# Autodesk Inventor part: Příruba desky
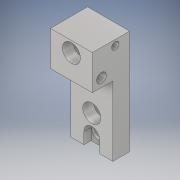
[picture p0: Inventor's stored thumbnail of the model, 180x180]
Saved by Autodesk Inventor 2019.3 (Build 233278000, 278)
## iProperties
Created: 2019-01
Part Number: Příruba desky
Material: Hliník 6061-AHC
Document SubType Name: Modeling
Designer: B-hon
Density: 2.7 g/cm^3
Appearance: Hliník – tmavý
Author: B-hon
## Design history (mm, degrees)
sketch "Náčrt1"
  geometry: L1 (-32.5, 40)-(32.5, 40); L2 (32.5, 40)-(32.5, -40); L3 (32.5, -40)-(-32.5, -40); L4 (-32.5, -40)-(-32.5, 40); L5 (-32.5, 40)-(32.5, -40); L6 (32.5, 40)-(-32.5, -40); 1 further point
  constraints: 12 end point, 2 midpoint, 2 parallel, 1 horizontal, 1 perpendicular
  dimensions: "d0" = 65 distance of L2.end L3.end; "d1" = 80 distance of L1.end L2.end
extrude "Vysunutí1" new body sketch "Náčrt1" distance "d2" = 26; taper "d3" = 0 deg
sketch "Náčrt2"
  geometry: L1 (-44.381, 28)-(47.748, 28); L2 (47.748, 28)-(47.748, 22); L3 (47.748, 22)-(-44.381, 22); L4 (-44.381, 22)-(-44.381, 28); L5 (-44.381, 28)-(47.748, 22); L6 (47.748, 28)-(-44.381, 22); L7 (-32.5, -40)-(32.5, -40) reference; L8 (-38.512, 18)-(43.239, 18); L9 (43.239, 18)-(43.239, -45.522); L10 (43.239, -45.522)-(-38.512, -45.522); L11 (-38.512, -45.522)-(-38.512, 18); L12 (-32.5, 40)-(-32.5, -40) reference; 2 further points
  constraints: 20 end point, 4 parallel, 2 horizontal, 2 midpoint, 2 perpendicular
  dimensions: "d4" = 6 distance of L1.end L2.end; "d5" = 65 distance from line of L7 point (1.683, 25); "d6" = 7 distance from line of L8 point (1.683, 25)
extrude "Vysunutí2" cut sketch "Náčrt2" distance "d10" = 14; taper "d11" = 0 deg
sketch "Náčrt3"
  geometry: L1 (-39.607, 44.84)-(-17.5, 44.84); L2 (-17.5, 44.84)-(-17.5, 11.926); L3 (-17.5, 11.926)-(-39.607, 11.926); L4 (-39.607, 11.926)-(-39.607, 44.84); L5 (17.5, 44.045)-(36.686, 44.045); L6 (36.686, 44.045)-(36.686, 9.931); L7 (36.686, 9.931)-(17.5, 9.931); L8 (17.5, 9.931)-(17.5, 44.045); L9 (-32.5, 40)-(-32.5, 18) reference; 1 further point
  constraints: 16 end point, 4 parallel, 2 horizontal, 2 perpendicular
  dimensions: "d12" = 35 distance between parallel lines of L8 L2; "d13" = 15 distance between parallel lines of L9 L2
extrude "Vysunutí3" cut sketch "Náčrt3" distance "d14" = 14; taper "d15" = 0 deg
sketch "Náčrt4"
  geometry: L1 (26, -58)-(14, -58) reference; L2 (0, 0)-(0, 22) reference; 2 further points
  dimensions: "d16" = 65 distance from line of L1 point (4.5, 7); "d17" = 4.5 distance from line of L2 point (4.5, 7)
hole "Díra1" sketch "Náčrt4" at (4.5, 7) diameter "d18" = 8; stored, may be unused: countersink angle "d22" = 90 deg, drill point angle "d24" = 118 deg; dims "d19" = 6, "d20" = 11, "d21" = 6.8, "d23" = 8
node "Upravit přímo1"
sketch "Náčrt6"
  geometry: L1 (32.5, -40)-(-32.5, -40) reference; C1 r 6.5 at (0, -30); 1 further point
  constraints: 1 centre point
  dimensions: "d39" = 13 diameter of C1; "d40" = 10 distance from line of L1 C1.centre
extrude "Vysunutí4" cut sketch "Náčrt6" distance "d41" = 8; taper "d42" = 0 deg
sketch "Náčrt7"
  geometry: L1 (-6.5, -61.308)-(6.5, -61.308); L2 (6.5, -61.308)-(6.5, -30.361); L3 (6.5, -30.361)-(-6.5, -30.361); L4 (-6.5, -30.361)-(-6.5, -61.308); L5 (-6.5, -61.308)-(6.5, -30.361); L6 (6.5, -61.308)-(-6.5, -30.361); 2 further points
  constraints: 12 end point, 2 midpoint, 2 parallel, 1 horizontal, 1 perpendicular
  dimensions: "d43" = 13 distance of L3.end L2.end
extrude "Vysunutí5" cut sketch "Náčrt7" distance "d44" = 6; taper "d45" = 0 deg
node "Upravit přímo2"
sketch "Náčrt9"
  geometry: L1 (17.5, 18)-(17.5, 45) reference; L2 (-6.5, -40)-(-32.5, -40) reference; 2 further points
  dimensions: "d58" = 17.5 distance from line of L1 point (0, -14); "d59" = 26 distance from line of L2 point (0, -14)
hole "Díra4" sketch "Náčrt9" at (0, -14) diameter "d60" = 8.4; stored, may be unused: countersink angle "d64" = 90 deg, drill point angle "d66" = 118 deg; dims "d61" = 16, "d62" = 15, "d63" = 9, "d65" = 8
sketch "Náčrt10"
  geometry: L1 (-48.128, 53.565)-(-17.5, 53.565); L2 (-17.5, 53.565)-(-17.5, -46.218); L3 (-17.5, -46.218)-(-48.128, -46.218); L4 (-48.128, -46.218)-(-48.128, 53.565); L5 (17.5, 54.3)-(38.723, 54.3); L6 (38.723, 54.3)-(38.723, -45.483); L7 (38.723, -45.483)-(17.5, -45.483); L8 (17.5, -45.483)-(17.5, 54.3); L9 (-17.5, 45)-(-17.5, 18) reference; L10 (17.5, 18)-(17.5, 45) reference; 1 further point
  constraints: 16 end point, 4 parallel, 2 horizontal, 2 perpendicular
  dimensions: "d67" = 0 distance between parallel lines of L9 L2; "d68" = 0 distance between parallel lines of L8 L10
extrude "Vysunutí6" cut sketch "Náčrt10" distance "d69" = 15; taper "d70" = 0 deg
node "Upravit přímo4"
sketch "Náčrt11"
  geometry: L1 (35, 29)-(0, 29) reference; L2 (35, 0)-(35, 29) reference; 2 further points
  dimensions: "d77" = 9 distance from line of L1 point (17.5, 20); "d78" = 17.5 distance from line of L2 point (17.5, 20)
hole "Díra5" sketch "Náčrt11" at (17.5, 20) diameter "d79" = 8.4; stored, may be unused: countersink angle "d83" = 90 deg, drill point angle "d85" = 118 deg; dims "d80" = 16, "d81" = 15, "d82" = 9, "d84" = 8
node "Upravit přímo5"
sketch "Náčrt12"
  geometry: L1 (14, 87)-(14, 0) reference; L2 (-17, 87)-(14, 87) reference; 2 further points
  dimensions: "d89" = 12 distance from line of L1 point (2, 82.5); "d90" = 4.5 distance from line of L2 point (2, 82.5)
hole "Díra6" sketch "Náčrt12" at (2, 82.5) diameter "d91" = 6; stored, may be unused: countersink angle "d95" = 90 deg, drill point angle "d97" = 118 deg; dims "d92" = 16, "d93" = 15, "d94" = 9, "d96" = 13
node "Těleso1"
feature "Posunout1" dims "d27" = 5
feature "Posunout2" dims "d48" = 3
feature "Posunout4" dims "d76" = 2
feature "Posunout5" dims "d88" = 2
other parameters: "d25" = 0, "d26" = 0, "d46" = 0, "d47" = 0, "d74" = 0, "d75" = 0, "d86" = 0, "d87" = 0
